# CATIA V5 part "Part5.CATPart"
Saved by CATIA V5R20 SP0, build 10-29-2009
Part number: Part5
Bounding box of the stored display mesh (mm): x 0 to 30, y -12 to 12, z -11.99 to 231.99
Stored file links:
  C:\Users\Orange\Desktop\Assembly Design-3\Part5.CATPart
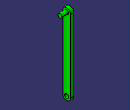
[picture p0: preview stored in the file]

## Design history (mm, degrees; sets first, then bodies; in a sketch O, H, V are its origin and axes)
Body1 (main body)
  Sketch1 on yz-plane, origin (0, 0, 0), H (0, 1, 0), V (0, 0, 1)
    construction line L1 (0, 0) -> (0, 220)
    line L2 (-12, 0) -> (-12, 220)
    line L3 (12, 220) -> (12, 0)
    arc A1 centre (0, 220) radius 12 from (-12, 220) to (12, 220) cw
    arc A2 centre (0, 0) radius 12 from (12, 0) to (-12, 0) cw
    circle A3 centre (0, 0) radius 6
    circle A4 centre (0, 220) radius 6
    length L1 = 220
    distance L1 L2 = 12
    radius A3 = 6
    radius A4 = 6
    vertical: L1 V
    tangency: A1 L2, A2 L2, A1 L3, A2 L3
  Pad1: profile Sketch1, direction (1, 0, 0), length 10
  Sketch2 on start face of Pad1, origin (0, 0, 0), H (0, -1, 0), V (0, 0, 1)
    projected circle E1 centre (0, 220) radius 6 from edge [face of Pad1 from Sketch1.A4 | start face of Pad1]
  Pad2: profile Sketch2, direction (1, 0, 0), length 30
